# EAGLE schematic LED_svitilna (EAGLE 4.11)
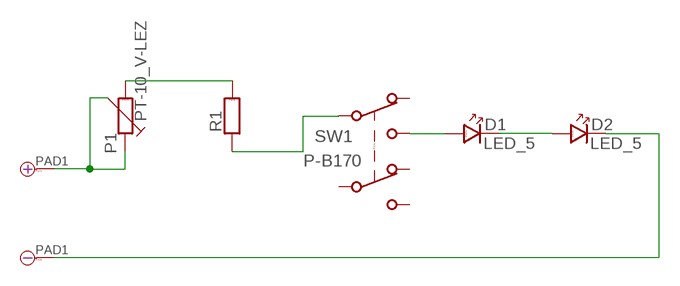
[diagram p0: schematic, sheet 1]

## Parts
D1  LED_5  [LED_5]
D2  LED_5  [LED_5]
P1  PT-10_V-LEZ  [PT10V]
PAD1  PAD_2+-  [PAD_2+-]
R1  R_7,5  [R-7,5]
SW1  P-B170  [P-B170]

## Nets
N$1: P1.1 P1.3 PAD1.+
N$2: P1.2 R1.2
N$3: R1.1 SW1.3(X1)
N$4: D1.A SW1.2(R1)
N$5: D1.K D2.A
N$6: D2.K PAD1.-
Unconnected: SW1.1(S1) SW1.4(S2) SW1.5(R2) SW1.6(X2)

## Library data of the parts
D1 D2 = #PaJa_14:LED: LED - jednobarevna
P1 = #PaJa_14:PT-10: Trimr - 10,3mm
PAD1 = #PaJa_14:PAD_2+-: Pajeci bod - 2,54 mm prumer, + a - , napajeci
R1 = #PaJa_14:R: Rezistor
SW1 = #PaJa_14:P-B170: Tlacitkovy prepinac - dvojity (8 x 8mm) P-B170G - s aretaci P-B170H - bez aretace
